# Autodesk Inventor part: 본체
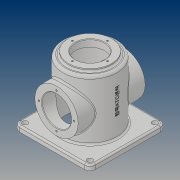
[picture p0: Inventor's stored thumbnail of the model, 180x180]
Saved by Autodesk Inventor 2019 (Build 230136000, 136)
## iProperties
Created: 2019-03
Part Number: 본체
Material: 일반
Document SubType Name: Modeling
Designer: PC312-14
Density: 1 g/cm^3
Appearance: 기본값
Author: PC312-14
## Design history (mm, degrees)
sketch "스케치1"
  geometry: C1 r 50 at (0, 0); 1 further point
  constraints: 1 centre point, 1 coincident
  dimensions: "d0" = 100 diameter of C1
extrude "돌출1" new body sketch "스케치1" distance "d1" = 110; taper "d2" = 0 deg
sketch "스케치2"
  geometry: C1 r 45 at (0, 0); 1 further point
  constraints: 1 centre point, 1 coincident
  dimensions: "d3" = 90 diameter of C1
extrude "돌출2" cut sketch "스케치2" distance "d4" = 102; taper "d5" = 0 deg
sketch "스케치3"
  geometry: L1 (-70, 70)-(70, 70); L2 (70, 70)-(70, -70); L3 (70, -70)-(-70, -70); L4 (-70, -70)-(-70, 70); L5 (-70, 70)-(70, -70); L6 (70, 70)-(-70, -70); C1 r 45 at (0, 0) reference; 1 further point
  constraints: 12 end point, 2 midpoint, 2 parallel, 1 horizontal, 1 perpendicular
  dimensions: "d6" = 140 distance of L2.end L3.end; "d7" = 140 distance of L1.end L2.end
extrude "돌출3" join sketch "스케치3" distance "d8" = 10; taper "d9" = 0 deg
node "작업 평면1"
sketch "스케치4"
  geometry: L1 (70, -10)-(-70, -10) reference; L2 (-70, 0)-(70, 0) reference; C1 r 40 at (0, 50); 2 further points
  constraints: 1 centre point, 1 midpoint, 1 vertical alignment
  dimensions: "d11" = 80 diameter of C1; "d12" = 60 distance from line of L1 C1.centre
extrude "돌출4" join sketch "스케치4" stored distance "d13" = 12; taper "d14" = 0 deg
sketch "스케치5" dims "d15" = 65
  geometry: C1 r 40 at (0, 0) reference; 3 further points
  constraints: 2 vertical alignment, 1 coincident, 2 other
hole "구멍1" sketch "스케치5" at (0, 32.5) diameter "d16" = 3.242; stored, may be unused: countersink angle "d20" = 90 deg, drill point angle "d22" = 118 deg; dims "d17" = 8, "d18" = 4, "d19" = 2, "d21" = 10
sketch "스케치6"
  geometry: C1 r 40 at (0, 0) reference; C2 r 27 at (0, 0); 1 further point
  constraints: 1 centre point, 1 coincident
  dimensions: "d26" = 54 diameter of C2
extrude "돌출5" cut sketch "스케치6" stored distance "d27" = 12; taper "d28" = 0 deg
sketch "스케치7"
  geometry: C1 r 40 at (0, 0); 1 further point
  constraints: 1 centre point, 1 coincident
  dimensions: "d29" = 80 diameter of C1
extrude "돌출6" join sketch "스케치7" distance "d30" = 5; taper "d31" = 0 deg
sketch "스케치8" dims "d32" = 65
  geometry: 3 further points
  constraints: 2 vertical alignment, 1 coincident, 2 other
hole "구멍2" sketch "스케치8" at (0, 32.5) diameter "d33" = 3.242; stored, may be unused: countersink angle "d37" = 90 deg, drill point angle "d39" = 118 deg; dims "d34" = 8, "d35" = 4, "d36" = 2, "d38" = 10
sketch "스케치9"
  geometry: C1 r 27 at (0, 0); 1 further point
  constraints: 1 centre point, 1 coincident
  dimensions: "d43" = 54 diameter of C1
extrude "돌출7" cut sketch "스케치9" distance "d44" = 13; taper "d45" = 0 deg
fillet "모깎기1" dims "d46" = 10
sketch "스케치10"
  geometry: A1 r 10 centre (60, -60) between (60, -70) and (70, -60) reference; A2 r 10 centre (60, 60) between (70, 60) and (60, 70) reference; A3 r 10 centre (-60, 60) between (-60, 70) and (-70, 60) reference; A4 r 10 centre (-60, -60) between (-70, -60) and (-60, -70) reference; 5 further points
  constraints: 4 coincident
hole "구멍3" sketch "스케치10" at (60, -60), (60, 60), (-60, 60), (-60, -60) diameter "d47" = 10; stored, may be unused: countersink angle "d51" = 90 deg, drill point angle "d53" = 118 deg; dims "d48" = 20, "d49" = 4, "d50" = 2, "d52" = 27.3
chamfer "모따기1" distance "d55" = 1; stored, may be unused: second distance "d56" = 2, angle "d57" = 45 deg
fillet "모깎기5" dims "d60" = 3
fillet "모깎기6" dims "d61" = 3
node "작업 평면2"
sketch "스케치11"
  geometry: L1 (-10, -60)-(-10, 60) reference; L2 (0, -60)-(0, 60) reference; 3 further points
  constraints: 1 horizontal alignment, 1 midpoint, 1 other
  dimensions: "d63" = 70 distance from line of L1 point (60, 0)
feature "엠보싱1" sketch "스케치11" dims "d64" = 0.5, "d65" = 0
fillet "모깎기7" dims "d66" = 5
fillet "모깎기8" dims "d67" = 3
fillet "모깎기9" dims "d68" = 3
node "솔리드1"
pattern_circular "원형 패턴1" dims angle "d24" = 360 deg
mirror "미러1"
pattern_circular "원형 패턴2" dims angle "d41" = 360 deg
other parameters: "d10" = 62, "d62" = 54
